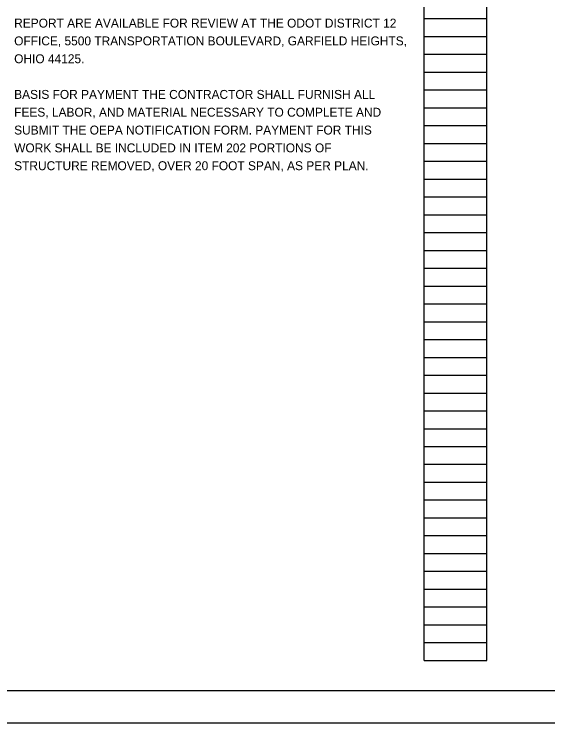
# Model space of a CAD drawing. Extents: x 0 to 34, y 0 to 22.
# Drawn here: x 17.24 to 25.62, y 0 to 11.13 of the extents above; entities that cross this region are included whole.
import ezdxf

# ---------------------------------------------------------------- set-up
doc = ezdxf.new("R2010")
doc.units = 0
for name, color, linetype in [('SH_Border', 7, 'Continuous'), ('SH_Cut_Line', 7, 'Continuous'), ('SH_Data', 7, 'Continuous'), ('SH_Text', 7, 'Continuous')]:
    doc.layers.add(name, color=color, linetype=linetype)

msp = doc.modelspace()

# ---------------------------------------------------------------- linework, layer by layer
at = {"layer": 'SH_Border'}
msp.add_lwpolyline([(1.5, 21.5), (33.5, 21.5), (33.5, 0.5), (1.5, 0.5)], close=True, dxfattribs=at)
at = {"layer": 'SH_Cut_Line'}
msp.add_lwpolyline([(0, 0), (34, 0), (34, 22), (0, 22)], close=True, dxfattribs=at)
at = {"layer": 'SH_Data'}
for p, q in [((23.68, 0.98), (23.68, 21.14)), ((24.66, 0.98), (24.66, 21.14)), ((23.68, 11.06), (24.66, 11.06)), ((23.68, 10.78), (24.66, 10.78)), ((23.68, 10.5), (24.66, 10.5)), ((23.68, 10.22), (24.66, 10.22)), ((23.68, 9.94), (24.66, 9.94)), ((23.68, 9.66), (24.66, 9.66)), ((23.68, 9.38), (24.66, 9.38)), ((23.68, 9.1), (24.66, 9.1)), ((23.68, 8.82), (24.66, 8.82)), ((23.68, 8.54), (24.66, 8.54)), ((23.68, 8.26), (24.66, 8.26)), ((23.68, 7.98), (24.66, 7.98)), ((23.68, 7.7), (24.66, 7.7)), ((23.68, 7.42), (24.66, 7.42)), ((23.68, 7.14), (24.66, 7.14)), ((23.68, 6.86), (24.66, 6.86)), ((23.68, 6.58), (24.66, 6.58)), ((23.68, 6.3), (24.66, 6.3)), ((23.68, 6.02), (24.66, 6.02)), ((23.68, 5.74), (24.66, 5.74)), ((23.68, 5.46), (24.66, 5.46)), ((23.68, 5.18), (24.66, 5.18)), ((23.68, 4.9), (24.66, 4.9)), ((23.68, 4.62), (24.66, 4.62)), ((23.68, 4.34), (24.66, 4.34)), ((23.68, 4.06), (24.66, 4.06)), ((23.68, 3.78), (24.66, 3.78)), ((23.68, 3.5), (24.66, 3.5)), ((23.68, 3.22), (24.66, 3.22)), ((23.68, 2.94), (24.66, 2.94)), ((23.68, 2.66), (24.66, 2.66)), ((23.68, 2.38), (24.66, 2.38)), ((23.68, 2.1), (24.66, 2.1)), ((23.68, 1.82), (24.66, 1.82)), ((23.68, 1.54), (24.66, 1.54)), ((23.68, 1.26), (24.66, 1.26)), ((23.68, 0.98), (24.66, 0.98))]:
    msp.add_line(p, q, dxfattribs=at)

# ---------------------------------------------------------------- texts
at = {"layer": 'SH_Text'}
for s, p in [('REPORT ARE AVAILABLE FOR REVIEW AT THE ODOT DISTRICT 12 ', (17.24, 10.92)), ('OFFICE, 5500 TRANSPORTATION BOULEVARD, GARFIELD HEIGHTS, ', (17.24, 10.64)), ('OHIO 44125. ', (17.24, 10.36)), ('BASIS FOR PAYMENT THE CONTRACTOR SHALL FURNISH ALL ', (17.24, 9.8)), ('FEES, LABOR, AND MATERIAL NECESSARY TO COMPLETE AND ', (17.24, 9.52)), ('SUBMIT THE OEPA NOTIFICATION FORM. PAYMENT FOR THIS ', (17.24, 9.24)), ('WORK SHALL BE INCLUDED IN ITEM 202 PORTIONS OF ', (17.24, 8.96)), ('STRUCTURE REMOVED, OVER 20 FOOT SPAN, AS PER PLAN.', (17.24, 8.68))]:
    msp.add_text(s, height=0.14, dxfattribs=at).set_placement(p)

doc.saveas('drawing.dxf')
